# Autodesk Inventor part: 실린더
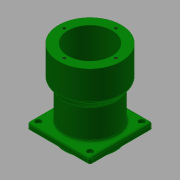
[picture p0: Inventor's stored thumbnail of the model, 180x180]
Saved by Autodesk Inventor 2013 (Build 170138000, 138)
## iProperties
Created: 2016-11
Part Number: 실린더
Material: 알루미늄 6061
Document SubType Name: Modeling
Designer: mduedu
Density: 2.71 g/cm^3
Mass: 592.083 g
Surface Area: 591.531 cm^2
Volume: 218.481 cm^3
Author: mduedu
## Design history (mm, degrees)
sketch "스케치1"
  geometry: L1 (0, 0)-(0, 110); L2 (30, 0)-(30, 110); L3 (30, 110)-(42.5, 110); L4 (42.5, 110)-(42.5, 70); L5 (42.5, 70)-(35, 60); L6 (35, 60)-(35, 0); L7 (35, 0)-(30, 0)
  constraints: 14 end point, 4 parallel, 2 horizontal alignment, 1 perpendicular, 1 vertical
  dimensions: "d0" = 110 distance of L1.start L1.end; "d1" = 60 diameter of L2.end L1; "d2" = 85 diameter of L3.end L1; "d3" = 70 diameter of L6.end L1; "d4" = 40 distance of L3.end L4.end; "d5" = 50 vertical distance of L5.end L3.end
revolve "회전1" sketch "스케치1" stored, may be unused: angle "d6" = 90 deg
node "작업 평면1"
sketch "스케치2"
  geometry: L1 (-42.5, -42.5)-(42.5, -42.5); L2 (42.5, -42.5)-(42.5, 42.5); L3 (42.5, 42.5)-(-42.5, 42.5); L4 (-42.5, 42.5)-(-42.5, -42.5); L5 (-42.5, -42.5)-(42.5, 42.5); L6 (42.5, -42.5)-(-42.5, 42.5); C1 r 35 at (0, 0) reference; C2 r 35 at (0, 0); 1 further point
  constraints: 12 end point, 2 midpoint, 2 parallel, 2 perpendicular, 1 centre point, 1 coincident, 1 concentric, 1 horizontal
  dimensions: "d8" = 85 distance of L2.end L3.end
extrude "돌출1" join sketch "스케치2" distance "d10" = 8; taper "d11" = 0 deg
fillet "모깎기1" dims "d12" = 3
fillet "모깎기2" dims "d13" = 3
chamfer "모따기1" distance "d14" = 1; stored, may be unused: second distance "d15" = 2, angle "d16" = 45 deg
chamfer "모따기2" distance "d17" = 5; stored, may be unused: second distance "d18" = 2, angle "d19" = 15 deg
sketch "스케치3"
  geometry: L1 (-35, -35)-(35, -35); L2 (35, -35)-(35, 35); L3 (35, 35)-(-35, 35); L4 (-35, 35)-(-35, -35); L5 (-35, -35)-(35, 35); L6 (35, -35)-(-35, 35); 5 further points
  constraints: 12 end point, 4 coincident, 2 midpoint, 2 parallel, 1 horizontal, 1 perpendicular
  dimensions: "d20" = 70 distance of L3.end L2.end; "d21" = 70 distance of L2.end L1.end
sketch "스케치4"
  geometry: 4 further points
  constraints: 4 other
hole "구멍1" sketch "스케치4" at (-35, 35), (35, 35), (35, -35), (-35, -35) diameter "d22" = 4.5; stored, may be unused: countersink angle "d26" = 90 deg, drill point angle "d28" = 0 deg; dims "d23" = 6, "d24" = 8, "d25" = 4.6, "d27" = 8
sketch "스케치5"
  geometry: 4 further points
  constraints: 4 other
hole "구멍2" sketch "스케치5" at (0, -35), (35, 0), (-35, 0), (0, 35) diameter "d29" = 4.134; stored, may be unused: countersink angle "d33" = 90 deg, drill point angle "d35" = 120 deg; dims "d30" = 7.5, "d31" = 4, "d32" = 2, "d34" = 10
node "솔리드1"
